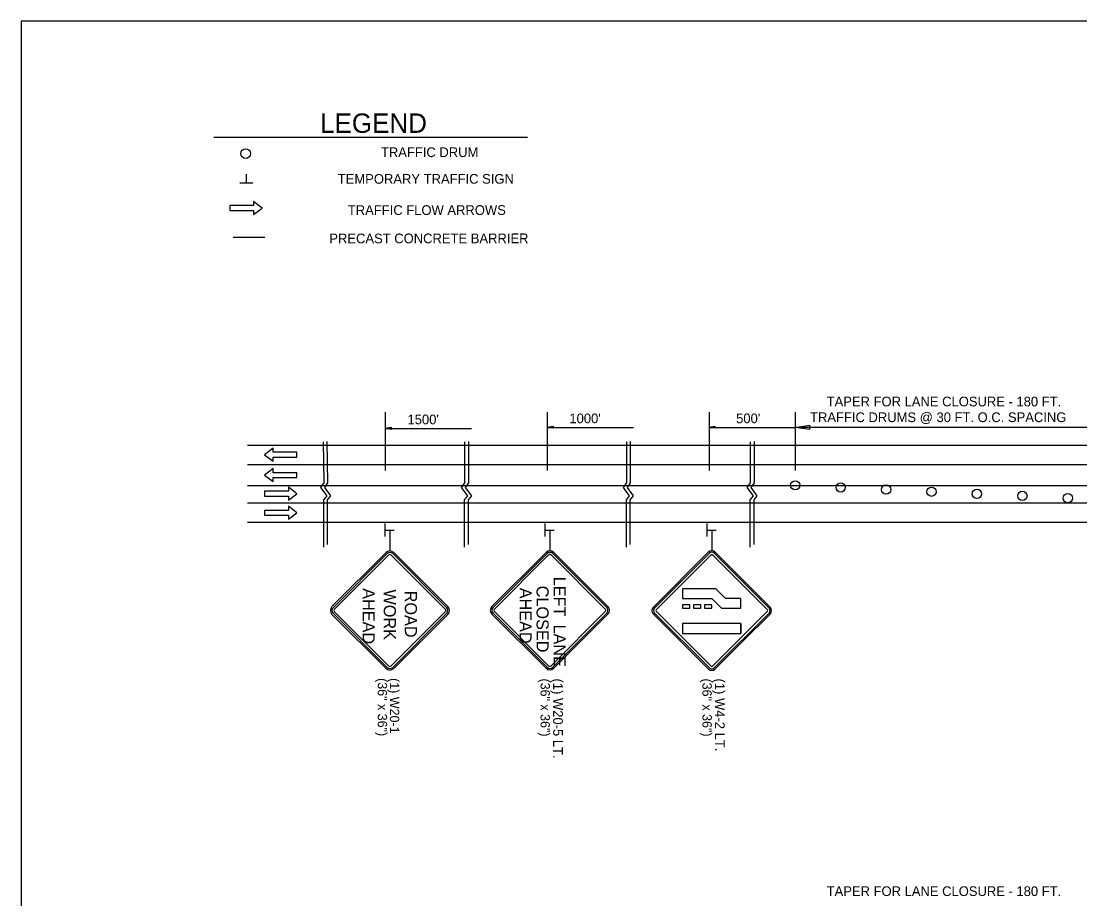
# Model space of a CAD drawing. Extents: x 1930579 to 1938013, y 596452 to 597673.
# Drawn here: x 1936313 to 1936967, y 597131 to 597673 of the extents above; entities that cross this region are included whole.
import ezdxf

# ---------------------------------------------------------------- set-up
doc = ezdxf.new("R2010")
doc.units = 0
for name, color, linetype in [('B_StampSCR', 7, 'Continuous'), ('Default', 7, 'Continuous'), ('P_TC_Signs_Permanent', 7, 'Continuous'), ('P_TC_Signs_Temporary', 7, 'Continuous'), ('R_Annotation', 7, 'Continuous'), ('R_Border', 7, 'Continuous'), ('R_MOT', 7, 'Continuous'), ('R_Striping', 7, 'Continuous')]:
    doc.layers.add(name, color=color, linetype=linetype)

msp = doc.modelspace()

# ---------------------------------------------------------------- linework, layer by layer
at = {"layer": 'B_StampSCR'}
msp.add_line((1937804.86, 597386.36), (1936452.69, 597386.36), dxfattribs=at)
at = {"layer": 'Default'}
for p, q in [((1936463.36, 597539.67), (1936443.86, 597539.67)), ((1936537.79, 597431.71), (1936537.79, 597395.8)), ((1936637.79, 597431.71), (1936637.79, 597395.8)), ((1936737.79, 597431.71), (1936737.79, 597395.8)), ((1936791.02, 597431.71), (1936791.02, 597395.8)), ((1936541.62, 597422.3), (1936537.79, 597421.72)), ((1936537.79, 597421.72), (1936591.02, 597421.72)), ((1936541.62, 597421.15), (1936537.79, 597421.72)), ((1936541.62, 597422.2), (1936538.43, 597421.72)), ((1936541.62, 597421.24), (1936538.43, 597421.72)), ((1936541.62, 597422.1), (1936539.09, 597421.72)), ((1936541.62, 597421.34), (1936539.09, 597421.72)), ((1936541.62, 597422.01), (1936539.73, 597421.72)), ((1936541.62, 597421.44), (1936539.73, 597421.72)), ((1936541.62, 597421.91), (1936540.37, 597421.72)), ((1936541.62, 597421.54), (1936540.37, 597421.72)), ((1936541.62, 597421.81), (1936541.01, 597421.72)), ((1936541.62, 597421.63), (1936541.01, 597421.72)), ((1936541.62, 597421.15), (1936541.62, 597422.3)), ((1936641.62, 597422.98), (1936637.79, 597422.4)), ((1936637.79, 597422.4), (1936691.02, 597422.4)), ((1936641.62, 597421.83), (1936637.79, 597422.4)), ((1936641.62, 597422.88), (1936638.43, 597422.4)), ((1936641.62, 597421.92), (1936638.43, 597422.4)), ((1936641.62, 597422.78), (1936639.09, 597422.4)), ((1936641.62, 597422.02), (1936639.09, 597422.4)), ((1936641.62, 597422.69), (1936639.73, 597422.4)), ((1936641.62, 597422.12), (1936639.73, 597422.4)), ((1936641.62, 597422.59), (1936640.37, 597422.4)), ((1936641.62, 597422.22), (1936640.37, 597422.4)), ((1936641.62, 597422.49), (1936641.01, 597422.4)), ((1936641.62, 597422.31), (1936641.01, 597422.4)), ((1936641.62, 597421.83), (1936641.62, 597422.98)), ((1936741.62, 597422.98), (1936737.79, 597422.4)), ((1936737.79, 597422.4), (1936791.02, 597422.4)), ((1936741.62, 597421.83), (1936737.79, 597422.4)), ((1936741.62, 597422.88), (1936738.43, 597422.4)), ((1936741.62, 597421.92), (1936738.43, 597422.4)), ((1936741.62, 597422.78), (1936739.09, 597422.4)), ((1936741.62, 597422.02), (1936739.09, 597422.4)), ((1936741.62, 597422.69), (1936739.73, 597422.4)), ((1936741.62, 597422.12), (1936739.73, 597422.4)), ((1936741.62, 597422.59), (1936740.37, 597422.4)), ((1936741.62, 597422.22), (1936740.37, 597422.4)), ((1936741.62, 597422.49), (1936741.01, 597422.4)), ((1936741.62, 597422.31), (1936741.01, 597422.4)), ((1936741.62, 597421.83), (1936741.62, 597422.98)), ((1936791.02, 597422.4), (1936799.89, 597423.73)), ((1937015.53, 597422.4), (1936791.02, 597422.4)), ((1936799.89, 597421.07), (1936791.02, 597422.4)), ((1936799.89, 597423.73), (1936799.89, 597421.07)), ((1937804.86, 597411.17), (1936452.69, 597411.17)), ((1937804.86, 597399.17), (1936452.69, 597399.17)), ((1937804.86, 597399.17), (1936452.69, 597399.17)), ((1937804.86, 597375.6), (1936452.69, 597375.6)), ((1937804.86, 597363.6), (1936452.69, 597363.6)), ((1936537.79, 597355), (1936537.79, 597362.98)), ((1936636.62, 597354.95), (1936636.62, 597362.93)), ((1936736.62, 597354.95), (1936736.62, 597362.93)), ((1936537.91, 597358.97), (1936543.36, 597358.97)), ((1936636.74, 597358.92), (1936642.18, 597358.92)), ((1936736.74, 597358.92), (1936742.18, 597358.92))]:
    msp.add_line(p, q, dxfattribs=at)
for points in [[(1936499.33, 597413.45), (1936499.72, 597388.21), (1936497.77, 597385.31), (1936501.57, 597380.12), (1936499.57, 597377.72), (1936499.56, 597348.37)], [(1936501.73, 597413.68), (1936502.12, 597388.11), (1936500.17, 597385.21), (1936503.96, 597380.02), (1936501.96, 597377.62), (1936501.96, 597350.06)], [(1936586.69, 597413.45), (1936586.69, 597388.21), (1936584.74, 597385.31), (1936588.54, 597380.12), (1936586.54, 597377.72), (1936586.54, 597348.37)], [(1936589.09, 597413.68), (1936589.09, 597388.11), (1936587.14, 597385.21), (1936590.94, 597380.02), (1936588.94, 597377.62), (1936588.94, 597350.06)], [(1936686.69, 597413.45), (1936686.69, 597388.21), (1936684.74, 597385.31), (1936688.54, 597380.12), (1936686.54, 597377.72), (1936686.54, 597348.37)], [(1936689.09, 597413.68), (1936689.09, 597388.11), (1936687.14, 597385.21), (1936690.94, 597380.02), (1936688.94, 597377.62), (1936688.94, 597350.06)], [(1936763.16, 597413.45), (1936763.16, 597388.21), (1936761.21, 597385.31), (1936765.01, 597380.12), (1936763.01, 597377.72), (1936763, 597348.37)], [(1936765.56, 597413.68), (1936765.56, 597388.11), (1936763.61, 597385.21), (1936767.4, 597380.02), (1936765.41, 597377.62), (1936765.4, 597350.06)]]:
    msp.add_lwpolyline(points, dxfattribs=at)
for centre, radius in [((1936451.57, 597591.57), 3), ((1936791.02, 597386.59), 2.87), ((1936819.09, 597385.28), 2.87), ((1936847.15, 597383.97), 2.87), ((1936875.21, 597382.65), 2.87), ((1936903.28, 597381.34), 2.87), ((1936931.34, 597380.03), 2.87), ((1936959.4, 597378.71), 2.87)]:
    msp.add_circle(centre, radius, dxfattribs=at)
at = {"layer": 'P_TC_Signs_Permanent'}
for p, q in [((1936737.34, 597345.24), (1936703.4, 597311.3)), ((1936775.52, 597311.3), (1936741.58, 597345.24)), ((1936703.4, 597307.05), (1936737.34, 597273.11)), ((1936757.46, 597301.13), (1936757.46, 597295.13))]:
    msp.add_line(p, q, dxfattribs=at)
for points in [[(1936704.03, 597310.66), (1936737.97, 597344.6)], [(1936739.04, 597343.54), (1936705.09, 597309.6)], [(1936773.82, 597309.6), (1936739.88, 597343.54)], [(1936740.94, 597344.6), (1936774.89, 597310.66)], [(1936737.97, 597273.75), (1936704.03, 597307.69)], [(1936705.09, 597308.75), (1936739.04, 597274.81)], [(1936739.88, 597274.81), (1936773.82, 597308.75)], [(1936774.89, 597307.69), (1936740.94, 597273.75)], [(1936741.58, 597273.11), (1936758.55, 597290.08), (1936775.52, 597307.05)]]:
    msp.add_lwpolyline(points, dxfattribs=at)
for points in [[(1936721.46, 597322.67), (1936721.46, 597316.67), (1936739.46, 597316.67), (1936745.46, 597310.67), (1936757.46, 597310.67), (1936757.46, 597316.67), (1936747.94, 597316.67), (1936741.94, 597322.67)], [(1936721.46, 597312.77), (1936721.46, 597310.67), (1936725.96, 597310.67), (1936725.96, 597312.77)], [(1936728.21, 597312.77), (1936728.21, 597310.67), (1936732.71, 597310.67), (1936732.71, 597312.77)], [(1936734.96, 597312.77), (1936734.96, 597310.67), (1936739.46, 597310.67), (1936739.46, 597312.77)], [(1936721.46, 597301.13), (1936721.46, 597295.13), (1936757.46, 597295.13), (1936757.46, 597301.13)]]:
    msp.add_lwpolyline(points, close=True, dxfattribs=at)
for centre, radius, start, end in [((1936739.46, 597343.12), 3, 45, 135), ((1936739.46, 597343.12), 2.1, 45, 135), ((1936739.46, 597343.12), 0.6, 45, 135), ((1936705.52, 597309.17), 3, 135, 225), ((1936705.52, 597309.17), 2.1, 135, 225), ((1936773.4, 597309.17), 2.1, 315, 45), ((1936773.4, 597309.17), 3, 315, 45), ((1936705.52, 597309.17), 0.6, 135, 225), ((1936773.4, 597309.17), 0.6, 315, 45), ((1936739.46, 597275.23), 3, 225, 315), ((1936739.46, 597275.23), 2.1, 225, 315), ((1936739.46, 597275.23), 0.6, 225, 315)]:
    msp.add_arc(centre, radius, start, end, dxfattribs=at)
at = {"layer": 'P_TC_Signs_Temporary'}
for p, q in [((1936504.84, 597311.64), (1936538.25, 597345.05)), ((1936505.5, 597310.98), (1936538.91, 597344.39)), ((1936506.43, 597310.05), (1936539.84, 597343.46)), ((1936541.43, 597343.46), (1936574.84, 597310.05)), ((1936542.36, 597344.39), (1936575.77, 597310.98)), ((1936543.02, 597345.05), (1936576.43, 597311.64)), ((1936603.66, 597311.72), (1936637.07, 597345.13)), ((1936604.33, 597311.05), (1936637.74, 597344.46)), ((1936605.25, 597310.13), (1936638.66, 597343.54)), ((1936640.26, 597343.54), (1936673.67, 597310.13)), ((1936641.18, 597344.46), (1936674.59, 597311.05)), ((1936641.85, 597345.13), (1936675.26, 597311.72)), ((1936538.25, 597273.46), (1936504.84, 597306.87)), ((1936538.91, 597274.12), (1936505.5, 597307.53)), ((1936539.84, 597275.05), (1936506.43, 597308.46)), ((1936574.84, 597308.46), (1936541.43, 597275.05)), ((1936575.77, 597307.53), (1936542.36, 597274.12)), ((1936576.43, 597306.87), (1936543.02, 597273.46)), ((1936637.07, 597273.53), (1936603.66, 597306.94)), ((1936637.74, 597274.2), (1936604.33, 597307.61)), ((1936638.66, 597275.12), (1936605.25, 597308.53)), ((1936673.67, 597308.53), (1936640.26, 597275.12)), ((1936674.59, 597307.61), (1936641.18, 597274.2)), ((1936675.26, 597306.94), (1936641.85, 597273.53))]:
    msp.add_line(p, q, dxfattribs=at)
for centre, radius, start, end in [((1936540.63, 597342.67), 3.38, 45, 135), ((1936540.63, 597342.67), 2.44, 45, 135), ((1936540.63, 597342.67), 1.12, 45, 135), ((1936639.46, 597342.74), 3.38, 45, 135), ((1936639.46, 597342.74), 2.44, 45, 135), ((1936639.46, 597342.74), 1.12, 45, 135), ((1936507.22, 597309.26), 3.38, 135, 225), ((1936507.22, 597309.26), 2.44, 135, 225), ((1936574.04, 597309.26), 2.44, 315, 45), ((1936574.04, 597309.26), 3.38, 315, 45), ((1936606.05, 597309.33), 3.38, 135, 225), ((1936606.05, 597309.33), 2.44, 135, 225), ((1936606.05, 597309.33), 1.13, 135, 225), ((1936672.87, 597309.33), 1.13, 315, 45), ((1936672.87, 597309.33), 2.44, 315, 45), ((1936672.87, 597309.33), 3.38, 315, 45), ((1936507.22, 597309.26), 1.13, 135, 225), ((1936574.04, 597309.26), 1.13, 315, 45), ((1936540.63, 597275.85), 3.38, 225, 315), ((1936540.63, 597275.85), 2.44, 225, 315), ((1936540.63, 597275.85), 1.12, 225, 315), ((1936639.46, 597275.92), 3.38, 225, 315), ((1936639.46, 597275.92), 2.44, 225, 315), ((1936639.46, 597275.92), 1.12, 225, 315)]:
    msp.add_arc(centre, radius, start, end, dxfattribs=at)
at = {"layer": 'R_Annotation'}
for p, q in [((1936431.79, 597601.6), (1936625.71, 597601.73)), ((1936451.95, 597573.4), (1936451.95, 597578.86)), ((1936455.93, 597573.29), (1936447.93, 597573.28)), ((1936540.63, 597358.97), (1936540.63, 597346.04)), ((1936639.46, 597358.91), (1936639.46, 597346.12)), ((1936739.46, 597358.91), (1936739.46, 597346.12))]:
    msp.add_line(p, q, dxfattribs=at)
at = {"layer": 'R_Border'}
msp.add_lwpolyline([(1938012.84, 597673.36), (1936312.84, 597673.36), (1936312.84, 596573.37), (1938012.84, 596573.37)], close=True, dxfattribs=at)
at = {"layer": 'R_MOT'}
msp.add_lwpolyline([(1936456.44, 597553.89), (1936461.63, 597557.89), (1936456.44, 597561.89), (1936456.44, 597559.39), (1936441.73, 597559.38), (1936441.73, 597556.38), (1936456.44, 597556.39)], close=True, dxfattribs=at)
at = {"layer": 'R_Striping'}
for points in [[(1936468.42, 597409.53), (1936463.23, 597405.53), (1936468.42, 597401.53), (1936468.42, 597404.03), (1936483.13, 597404.03), (1936483.13, 597407.03), (1936468.42, 597407.03)], [(1936468.42, 597396.9), (1936463.23, 597392.9), (1936468.42, 597388.9), (1936468.42, 597391.4), (1936483.13, 597391.4), (1936483.13, 597394.4), (1936468.42, 597394.4)], [(1936477.94, 597377.39), (1936483.13, 597381.39), (1936477.94, 597385.39), (1936477.94, 597382.89), (1936463.23, 597382.89), (1936463.23, 597379.89), (1936477.94, 597379.89)], [(1936477.94, 597365.61), (1936483.13, 597369.61), (1936477.94, 597373.61), (1936477.94, 597371.11), (1936463.23, 597371.11), (1936463.23, 597368.11), (1936477.94, 597368.11)]]:
    msp.add_lwpolyline(points, close=True, dxfattribs=at)

# ---------------------------------------------------------------- texts
at = {"layer": 'Default'}
for s, p in [('TAPER FOR LANE CLOSURE - 180 FT.', (1936810.44, 597435.36)), ("1500'", (1936551.51, 597424.3)), ("1000'", (1936651.51, 597424.96)), ("500'", (1936754.51, 597424.96)), ('TRAFFIC DRUMS @ 30 FT. O.C. SPACING', (1936800.17, 597425.65)), ('TAPER FOR LANE CLOSURE - 180 FT.', (1936810.44, 597132.84))]:
    msp.add_text(s, height=6, rotation=360, dxfattribs=at).set_placement(p)
at = {"layer": 'P_TC_Signs_Temporary'}
for s, p in [(' AHEAD ', (1936620.71, 597326.1)), ('CLOSED', (1936631.21, 597324.58)), ('LEFT\u2002LANE', (1936641.71, 597330.13)), (' AHEAD ', (1936523.8, 597325.8)), ('WORK', (1936536.82, 597322.25)), (' ROAD ', (1936549.85, 597324.28))]:
    msp.add_text(s, height=7.5, rotation=270, dxfattribs=at).set_placement(p)
at = {"layer": 'R_Annotation'}
for s, height, rotation, p in [('LEGEND', 12, 0.03878, (1936497.52, 597604.33)), ('TRAFFIC DRUM', 6, 0.03876, (1936535.11, 597589.37)), ('TEMPORARY TRAFFIC SIGN', 6, 0.03876, (1936508.44, 597572.89)), ('TRAFFIC FLOW ARROWS', 6, 0.03876, (1936514.64, 597553.61)), ('PRECAST CONCRETE BARRIER', 6, 0.03876, (1936503.2, 597536.1)), ('(36" x 36")', 5.76, 270, (1936533.14, 597267.47)), ('(1) W20-1', 5.76, 270, (1936540.63, 597267.47)), ('(36" x 36")', 5.76, 270, (1936633.7, 597267.23)), ('(1) W20-5 LT.', 6, 270, (1936641.47, 597267.23)), ('(36" x 36")', 5.76, 270, (1936733.7, 597267.23)), ('(1) W4-2 LT.', 6, 270, (1936741.47, 597267.23))]:
    msp.add_text(s, height=height, rotation=rotation, dxfattribs=at).set_placement(p)

doc.saveas('drawing.dxf')
